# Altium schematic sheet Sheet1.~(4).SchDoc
size 431 x 279 mm; SheetNumber: 1; SheetTotal: 1; ENG_APP_DATE: --/--/--; DSN_APP_DATE: --/--/--; CHK_APP_DATE: --/--/--
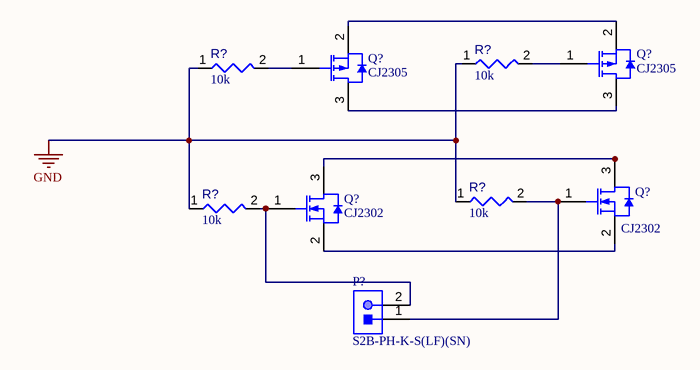
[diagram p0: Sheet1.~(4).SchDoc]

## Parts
(Parts that share a designator on the sheet are numbered #1, #2 ... from top to bottom, then left to right.)
P?  S2B-PH-K-S(LF)(SN)  [JST-S2B-PH-K-S_V]
Q?#1  CJ2305  [JSCJ-SOT23-3_V]
Q?#2  CJ2305  [JSCJ-SOT23-3_V]
Q?#3  CJ2302  [JSCJ-SOT23-3_V]
Q?#4  CJ2302  [JSCJ-SOT23-3_V]
R?#1  value 10k  [RESC0402(1005)_L]  (hidden comment: 10KR2F)
R?#2  value 10k  [RESC0402(1005)_L]  (hidden comment: 10KR2F)
R?#3  value 10k  [RESC0402(1005)_L]  (hidden comment: 10KR2F)
R?#4  value 10k  [RESC0402(1005)_L]  (hidden comment: 10KR2F)

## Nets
GND: R?#1.1 R?#2.1 R?#3.1 R?#4.1
NetP?_1: P?.1 Q?#3.1(G) R?#3.2
NetP?_2: P?.2 Q?#4.1(G) R?#4.2
NetQ?#1_1: Q?#1.1(GATE) R?#1.2
NetQ?#1_2: Q?#1.2(SOURCE) Q?#2.2(SOURCE)
NetQ?#1_3: Q?#1.3(DRAIN) Q?#2.3(DRAIN)
NetQ?#2_1: Q?#2.1(GATE) R?#2.2
NetQ?#3_2: Q?#3.2(S) Q?#4.2(S)
NetQ?#3_3: Q?#3.3(D) Q?#4.3(D)

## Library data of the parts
P? = CMP-002-00030-2: Male Header, Pitch 2 mm, 1 x 2 Position, Height 4.8 mm, Tail Length 3.4 mm, -25 to 85 degC, RoHS, Bulk; Manufacturer: Japan Solderless Terminals
Q?#1 Q?#2 = CMP-013-00015-3: P-Channel Plastic Encapsulate MOSFET, 12 V, 4.1 A, 3-Pin SOT23, Tape and Reel; Manufacturer: Jiangsu Changjiang Electronics Technology; Package Version: Rev. E, 09/2009
Q?#3 Q?#4 = CMP-013-00014-3: N-Channe Plastic Encapsulate MOSFET, 20 V, 2.1 A, 3-Pin SOT23, Tape and Reel; Manufacturer: Jiangsu Changjiang Electronics Technology; Package Version: Rev. E, 09/2009
R?#1-R?#4 = CMP-009-00066-2: 10K 0.063W 1% 0402 (1005 Metric)  SMD; Power: 63mW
